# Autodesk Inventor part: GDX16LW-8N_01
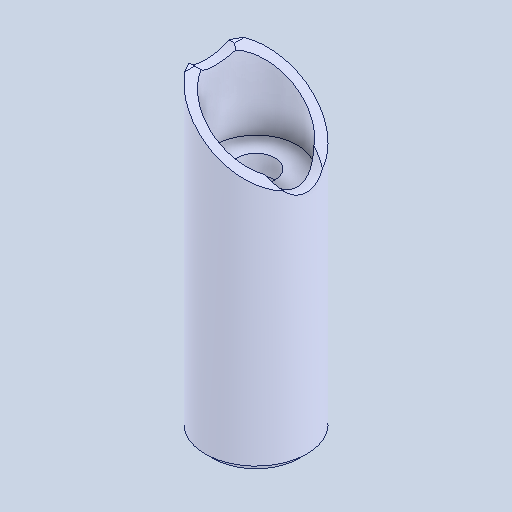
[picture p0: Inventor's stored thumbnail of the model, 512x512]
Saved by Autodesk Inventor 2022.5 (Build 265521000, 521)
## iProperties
Created: 2024-06
Part Number: GDX16LW-8N_01
Material: 一般
Document SubType Name: Modeling
Designer: ImaoCorp
Density: 1 g/cm^3
Appearance: 既定
Author: ImaoCorp
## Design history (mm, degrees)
feature "GDX16LW-8N_01"
node "ソリッド1"
